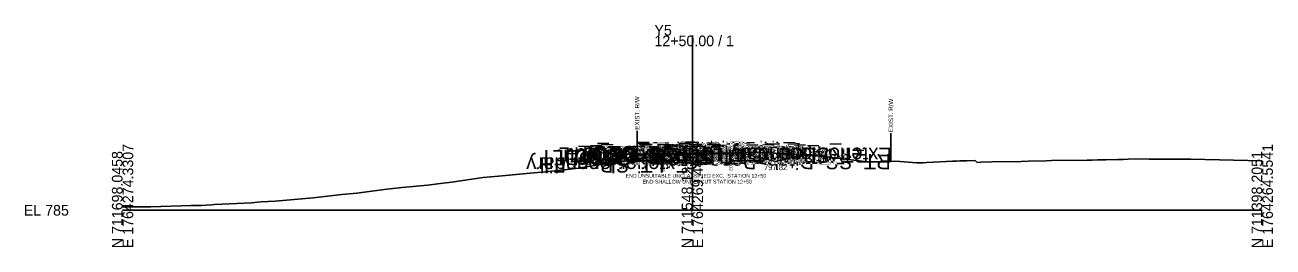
# Model space of a CAD drawing. Extents: x -26 to 303, y -10 to 4039.
# Drawn here: x -25.7 to 302.8, y 2490.3 to 2548.8 of the extents above; entities that cross this region are included whole.
import ezdxf

# ---------------------------------------------------------------- set-up
doc = ezdxf.new("R2010")
doc.units = 0
for name, color, linetype in [('Default', 7, 'Continuous'), ('Exist CMT Pavement', 7, 'Continuous'), ('Exist Cross Section Cell', 7, 'Continuous'), ('Exist XS Center Line Elevation Label', 7, 'Continuous'), ('Exist XS Ground Line', 7, 'Continuous'), ('Old_Level_10', 7, 'Continuous'), ('Prop CMT Pvmt Course 1', 7, 'Continuous'), ('Prop CMT Pvmt Course 3', 7, 'Continuous'), ('Prop CMT Pvmt Surface', 7, 'Continuous'), ('Prop CMT Pvmt Surface Shoulder', 7, 'Continuous'), ('Prop CMT Shld Paved Course 1', 7, 'Continuous'), ('Prop CMT Shld Paved Course 3', 7, 'Continuous'), ('Prop CMT Slope Grass', 7, 'Continuous'), ('Prop CMT Subgrade Earthwork', 7, 'Continuous'), ('Prop Road Sect_ Recs - UC (Outline)', 7, 'Continuous'), ('Prop Shade Light', 7, 'Continuous'), ('Prop XS Ditch Standard Text', 7, 'Continuous'), ('Prop XS Earthwork Shape', 7, 'Continuous'), ('Prop XS Earthwork Unsuitable Unclassified', 7, 'Continuous'), ('Prop XS SE Text', 7, 'Continuous'), ('Prop XS Side Slope Text', 7, 'Continuous'), ('Prop XS Wedging', 7, 'Continuous'), ('Scratch_Level_4', 7, 'Continuous')]:
    doc.layers.add(name, color=color, linetype=linetype)

msp = doc.modelspace()

# ---------------------------------------------------------------- linework, layer by layer
at = {"layer": 'Exist CMT Pavement'}
msp.add_lwpolyline([(142.35, 2514.56), (143.61, 2514.63), (144.37, 2514.67), (146.05, 2514.72), (146.87, 2514.74), (148.64, 2514.77), (149.38, 2514.78), (150, 2514.79), (151.22, 2514.81), (151.88, 2514.81), (152.49, 2514.82), (154.38, 2514.83), (156.39, 2514.83), (156.88, 2514.82), (158.98, 2514.85), (159.32, 2514.84), (160, 2514.85)], dxfattribs=at)
at = {"layer": 'Exist Cross Section Cell'}
for p, q in [((150, 2500), (150, 2546.03)), ((0, 2500), (150, 2500)), ((150, 2500), (300, 2500))]:
    msp.add_line(p, q, dxfattribs=at)
at = {"layer": 'Exist XS Ground Line'}
msp.add_lwpolyline([(0, 2500.92), (2.64, 2500.89), (7.4, 2500.88), (18.1, 2501.29), (19.06, 2501.29), (20.7, 2501.3), (23.39, 2501.47), (24.22, 2501.48), (33.96, 2501.98), (36.48, 2502.21), (40.21, 2502.44), (50.17, 2503.3), (57.71, 2504.15), (61.65, 2504.54), (69.58, 2505.54), (73.64, 2505.98), (80.28, 2506.65), (82.99, 2506.95), (86.55, 2507.43), (94.91, 2508.61), (99, 2509), (107.32, 2509.76), (111.28, 2510.11), (116.36, 2510.62), (119.94, 2511.11), (123.15, 2511.6), (129.98, 2512.69), (142.19, 2514.55), (143.61, 2514.63), (144.37, 2514.67), (146.05, 2514.72), (146.87, 2514.74), (148.64, 2514.77), (149.38, 2514.78), (150, 2514.79), (151.22, 2514.81), (151.88, 2514.81), (152.49, 2514.82), (154.38, 2514.83), (156.39, 2514.83), (156.88, 2514.82), (158.98, 2514.85), (159.32, 2514.84), (160.11, 2514.85), (162.42, 2515.11), (166.07, 2515.34), (168.28, 2515.17), (169.83, 2515.16), (171.35, 2515.01), (175.02, 2514.75), (179.57, 2514.46), (184.07, 2514.27), (185.54, 2514.04), (186.13, 2513.97), (195.98, 2512.8), (199.09, 2512.79), (201.04, 2512.82), (203.54, 2512.97), (209.06, 2512.48), (209.95, 2512.51), (210.69, 2512.53), (211.75, 2512.58), (213.47, 2512.68), (218.43, 2512.92), (219.59, 2512.98), (220.43, 2513.04), (221.03, 2513.03), (222.2, 2513.06), (224.43, 2513.1), (224.93, 2512.6), (225.95, 2512.66), (228.81, 2512.73), (236.56, 2512.84), (238.35, 2512.9), (243.15, 2513.05), (244.5, 2513.08), (253.91, 2513.19), (255.19, 2513.24), (256.69, 2513.33), (258.85, 2513.33), (261.95, 2513.38), (263.37, 2513.39), (264.73, 2513.42), (267.61, 2513.53), (270.27, 2513.46), (271.92, 2513.46), (281.18, 2513.48), (300, 2512.99)], dxfattribs=at)
at = {"layer": 'Old_Level_10'}
for p, q in [((135.45, 2520.93), (135.45, 2513.53)), ((202.25, 2520.3), (202.25, 2512.89)), ((142.19, 2514.55), (142.19, 2512.5)), ((160.11, 2514.85), (160.11, 2512.8))]:
    msp.add_line(p, q, dxfattribs=at)
at = {"layer": 'Prop CMT Pvmt Course 1'}
for points in [[(150, 2515.04), (140, 2514.94)], [(140, 2514.94), (140, 2514.69)], [(140, 2514.69), (142.35, 2514.71)], [(142.35, 2514.84), (150, 2514.92)], [(142.35, 2514.71), (142.35, 2514.84)], [(150, 2515.04), (160, 2515.14)], [(150, 2514.79), (150, 2515.04)], [(150, 2514.92), (150, 2514.79), (150, 2514.79)], [(150, 2514.79), (150, 2514.92), (150, 2514.92), (150, 2514.79), (150, 2514.79)], [(160, 2514.89), (150, 2514.79)], [(160, 2515.14), (160, 2514.89)]]:
    msp.add_lwpolyline(points, dxfattribs=at)
at = {"layer": 'Prop CMT Pvmt Course 3'}
for points in [[(142.35, 2514.71), (140, 2514.69)], [(140, 2514.69), (140, 2514.27)], [(140.01, 2514.27), (142.36, 2514.3)], [(142.35, 2514.3), (142.35, 2514.71)], [(160, 2514.89), (160, 2514.56)]]:
    msp.add_lwpolyline(points, dxfattribs=at)
at = {"layer": 'Prop CMT Pvmt Surface'}
for points in [[(150, 2515.04), (140, 2514.94)], [(150, 2515.04), (160, 2515.14)]]:
    msp.add_lwpolyline(points, dxfattribs=at)
at = {"layer": 'Prop CMT Pvmt Surface Shoulder'}
for points in [[(140, 2514.94), (140, 2514.94)], [(160, 2515.14), (160, 2515.14)]]:
    msp.add_lwpolyline(points, dxfattribs=at)
at = {"layer": 'Prop CMT Shld Paved Course 1'}
for points in [[(140, 2514.94), (139.74, 2514.68)], [(139.74, 2514.68), (140, 2514.69)], [(140, 2514.94), (140, 2514.94)], [(140, 2514.69), (140, 2514.94)], [(160, 2515.14), (160, 2515.14)], [(160, 2515.14), (160.26, 2514.88)], [(160, 2514.89), (160, 2515.14)], [(160.26, 2514.88), (160, 2514.89)]]:
    msp.add_lwpolyline(points, dxfattribs=at)
at = {"layer": 'Prop CMT Shld Paved Course 3'}
for points in [[(139.74, 2514.68), (139.32, 2514.26)], [(139.32, 2514.26), (140.01, 2514.27)], [(139.4, 2514.34), (139.4, 2514.34)], [(140, 2514.69), (139.74, 2514.68)], [(160, 2514.89), (160.26, 2514.88)], [(160.6, 2514.54), (160, 2514.56)], [(160.26, 2514.88), (160.6, 2514.54)], [(160.6, 2514.54), (160.6, 2514.54)]]:
    msp.add_lwpolyline(points, dxfattribs=at)
at = {"layer": 'Prop CMT Slope Grass'}
for points in [[(140, 2514.94), (136, 2514.62), (125.3, 2511.94)], [(160, 2515.14), (164, 2514.82), (172, 2512.82), (178.76, 2514.51)]]:
    msp.add_lwpolyline(points, dxfattribs=at)
at = {"layer": 'Prop CMT Subgrade Earthwork'}
for p, q in [((142.35, 2514.3), (140.01, 2514.27)), ((142.35, 2514.3), (142.35, 2514.56)), ((160, 2514.56), (160, 2514.85))]:
    msp.add_line(p, q, dxfattribs=at)
for points in [[(139.32, 2514.26), (138.74, 2514.84)], [(140.01, 2514.27), (139.32, 2514.26)], [(160, 2514.56), (160.6, 2514.54)], [(160.6, 2514.54), (161.1, 2515.05)]]:
    msp.add_lwpolyline(points, dxfattribs=at)
at = {"layer": 'Prop Road Sect_ Recs - UC (Outline)'}
for p, q in [((134.78, 2513), (134.78, 2513.42)), ((142.35, 2513), (142.35, 2514.05)), ((160, 2513), (160, 2514.22)), ((168, 2513), (168, 2513.82)), ((134.78, 2513), (142.35, 2513)), ((160, 2513), (168, 2513))]:
    msp.add_line(p, q, dxfattribs=at)
at = {"layer": 'Prop Shade Light'}
for p, q in [((138.53, 2513.99), (134.78, 2513.42)), ((134.78, 2513.42), (134.78, 2513)), ((140.39, 2514.28), (138.53, 2513.99)), ((142.36, 2514.3), (140.39, 2514.28)), ((140.39, 2514.28), (140.39, 2514.28)), ((142.35, 2513), (142.36, 2514.3)), ((160.6, 2514.54), (160, 2514.56)), ((160, 2514.56), (160, 2513)), ((168, 2513.82), (166.94, 2514.08)), ((168, 2513), (168, 2513.82)), ((134.78, 2513), (142.35, 2513)), ((160, 2513), (168, 2513))]:
    msp.add_line(p, q, dxfattribs=at)
msp.add_lwpolyline([(166.94, 2514.08), (164, 2514.82), (161.57, 2515.01), (161, 2514.95), (160.6, 2514.54)], dxfattribs=at)
at = {"layer": 'Prop XS Earthwork Shape'}
for points in [[(129.98, 2512.69), (140.39, 2514.28), (140.01, 2514.27), (139.32, 2514.26), (138.74, 2514.84), (136, 2514.62), (125.3, 2511.94)], [(142.19, 2514.55), (142.35, 2514.56), (142.35, 2514.3), (140.39, 2514.28)], [(160, 2514.56), (160.6, 2514.54), (161, 2514.95), (160.11, 2514.85), (160, 2514.85)], [(161, 2514.95), (161.57, 2515.01), (161.1, 2515.05)], [(161.57, 2515.01), (164, 2514.82), (172, 2512.82), (178.76, 2514.51), (175.02, 2514.75), (171.35, 2515.01), (169.83, 2515.16), (168.28, 2515.17), (166.07, 2515.34), (162.42, 2515.11)]]:
    msp.add_lwpolyline(points, close=True, dxfattribs=at)
at = {"layer": 'Prop XS Earthwork Unsuitable Unclassified'}
for p, q in [((160.11, 2514.85), (160, 2514.85)), ((160, 2514.85), (160, 2514.56)), ((160, 2514.56), (160.6, 2514.54)), ((161.57, 2515.01), (160.11, 2514.85)), ((164, 2514.82), (172, 2512.82)), ((172, 2512.82), (178.76, 2514.51))]:
    msp.add_line(p, q, dxfattribs=at)
for points in [[(160.6, 2514.54), (161, 2514.95), (161.57, 2515.01), (164, 2514.82)], [(178.76, 2514.51), (175.02, 2514.75), (171.35, 2515.01), (169.83, 2515.16), (168.28, 2515.17), (166.07, 2515.34), (162.42, 2515.11), (161.57, 2515.01)]]:
    msp.add_lwpolyline(points, dxfattribs=at)
at = {"layer": 'Prop XS Wedging'}
for p, q in [((150, 2514.79), (140, 2514.69)), ((150, 2514.79), (142.35, 2514.71)), ((142.35, 2514.71), (142.35, 2514.56)), ((142.35, 2514.71), (142.35, 2514.71)), ((142.35, 2514.56), (143.61, 2514.63)), ((143.61, 2514.63), (144.37, 2514.67)), ((148.64, 2514.77), (149.38, 2514.78)), ((149.38, 2514.78), (150, 2514.79)), ((160, 2514.89), (153.14, 2514.82)), ((153.14, 2514.82), (154.38, 2514.83)), ((154.38, 2514.83), (156.39, 2514.83)), ((158.98, 2514.85), (159.32, 2514.84)), ((159.32, 2514.84), (160, 2514.85)), ((160, 2514.85), (160, 2514.89))]:
    msp.add_line(p, q, dxfattribs=at)
for points in [[(144.37, 2514.67), (146.05, 2514.72), (146.87, 2514.74), (148.64, 2514.77)], [(156.39, 2514.83), (156.88, 2514.82), (158.98, 2514.85)]]:
    msp.add_lwpolyline(points, dxfattribs=at)

# ---------------------------------------------------------------- texts
at = {"layer": 'Default'}
msp.add_text('-', height=0.0001, dxfattribs=at).set_placement((0, 2500))
at = {"layer": 'Exist Cross Section Cell'}
for s, p in [('Y5', (140, 2546.03)), ('12+50.00 / 1', (140, 2543.23)), ('EL 785', (-26, 2498.6))]:
    msp.add_text(s, height=2.8, dxfattribs=at).set_placement(p)
for s, p in [('E 1764274.3307', (2.8, 2490)), ('E 1764269.4424', (152.8, 2490)), ('E 1764264.5541', (302.8, 2490)), ('N 711698.0458', (0, 2490)), ('N 711548.1254', (150, 2490)), ('N 711398.2051', (300, 2490))]:
    msp.add_text(s, height=2.8, rotation=90, dxfattribs=at).set_placement(p)
at = {"layer": 'Exist XS Center Line Elevation Label'}
for s, p in [('799.79', (147.87, 2512.79)), ('END SHALLOW UNDERCUT STATION 12+50', (136.86, 2507.03))]:
    msp.add_text(s, height=1, dxfattribs=at).set_placement(p)
at = {"layer": 'Old_Level_10'}
for s, height, p in [('EXIST. R/W', 1.181, (136.04, 2521.23)), ('EXIST. R/W', 1.181, (202.84, 2520.6)), ('EOP', 0.787, (142.58, 2510.1)), ('EOP', 0.787, (160.51, 2510.4))]:
    msp.add_text(s, height=height, rotation=90, dxfattribs=at).set_placement(p)
at = {"layer": 'Prop XS Ditch Standard Text'}
msp.add_text('797.82', height=1.5, dxfattribs=at).set_placement((168.84, 2510.57))
at = {"layer": 'Prop XS Earthwork Unsuitable Unclassified'}
msp.add_text('END UNSUITABLE UNCLASSIFIED EXC.  STATION 12+50', height=1, dxfattribs=at).set_placement((132.41, 2508.59))
at = {"layer": 'Prop XS SE Text'}
for p in [(142.54, 2515.97), (152.54, 2516.07)]:
    msp.add_text('0.010', height=1.5, rotation=0.5729, dxfattribs=at).set_placement(p)
at = {"layer": 'Prop XS Side Slope Text'}
for rotation, p in [(14.0362, (129.31, 2513.72)), (345.9638, (167.03, 2514.84)), (14.0362, (174.04, 2514.1))]:
    msp.add_text('4:1', height=1.5, rotation=rotation, dxfattribs=at).set_placement(p)
at = {"layer": 'Scratch_Level_4'}
for s, p in [('LT_Sub_OSS_DLT', (156.01, 2515.88)), ('LT_Sub_Trench_Out', (164.51, 2516)), ('LT_GS_OS_CTL', (155.62, 2516.62)), ('LT_PS3_Shelf_Out', (163.59, 2516.34)), ('LT_PV1_OEOT', (157.63, 2516.94)), ('LT_PS1_OEOP', (157.9, 2516.94)), ('LT_PS3_OEOP', (158.35, 2516.34)), ('LT_PV1_OEEOP', (162.05, 2516.84)), ('LT_PS2_OEOP', (158.66, 2516.68)), ('LT_PV2_OEOT', (158.64, 2516.69)), ('LT_PV3_OEOT', (158.67, 2516.36)), ('LT_Sub_OEOT', (158.11, 2516.02)), ('LT_PV2_OEEOP', (163.06, 2516.71)), ('LT_PV3_OEEOP', (163.09, 2516.38)), ('LT_Sub_OEEOP', (162.52, 2516.05)), ('RT_PV1_OEEOP', (170.2, 2516.92)), ('RT_PV2_OEEOP', (171.21, 2516.79)), ('RT_PV3_OEEOP', (171.24, 2516.46)), ('RT_Sub_OEEOP', (170.67, 2516.12)), ('RT_PV1_IEEOP', (169.32, 2516.92)), ('LT_PV1_IEEOP', (168.82, 2516.92)), ('RT_PV2_IEEOP', (170.33, 2516.79)), ('LT_PV2_IEEOP', (169.82, 2516.79)), ('RT_Sub_Trench_Out', (186.88, 2516.2)), ('PV1_PGL', (160.68, 2517.04)), ('PV2_PGL', (161.68, 2516.79)), ('RT_PS3_Shelf_Out', (185.28, 2516.54)), ('RT_PV1_OEOT', (178.14, 2517.14)), ('RT_PS1_OEOP', (178.41, 2517.14)), ('RT_PV2_OEOT', (179.15, 2516.89)), ('RT_PV3_OEOT', (179.18, 2516.56)), ('RT_Sub_OEOT', (178.61, 2516.22)), ('RT_PS2_OEOP', (179.67, 2516.88)), ('RT_PS3_OEOP', (180.04, 2516.54)), ('RT_GS_OS_CTL', (184.12, 2516.82)), ('RT_Sub_OSS_DLT', (190.4, 2516.08)), ('Exterior Boundary', (202.53, 2516.51)), ('RT_Slope_Cut', (196.33, 2516.51)), ('Exterior Boundary', (149.07, 2513.94)), ('LT_Slope_Fill', (142.57, 2513.94)), ('LT_Slope_Fill', (142.57, 2513.94)), ('RT_SS_Ditch_Base_Out', (202.23, 2514.82))]:
    msp.add_text(s, height=4, rotation=180, dxfattribs=at).set_placement(p)

doc.saveas('drawing.dxf')
